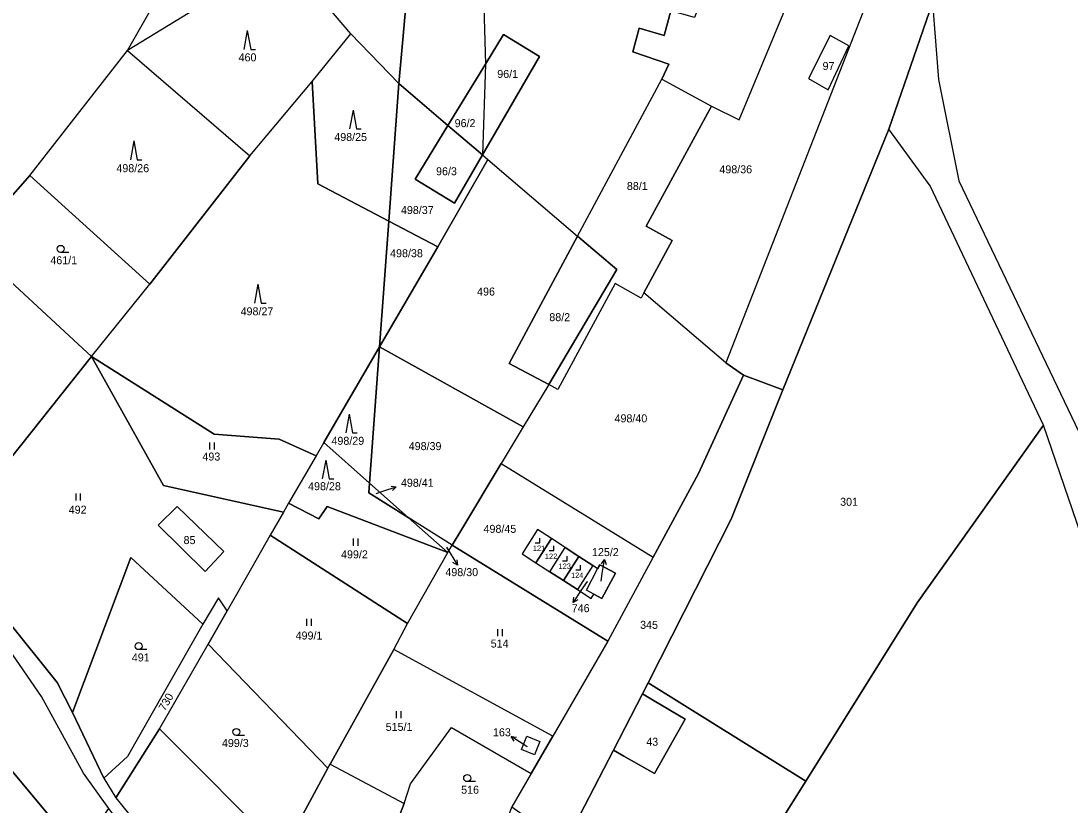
# Model space of a CAD drawing. Extents: x -590606 to -587796, y -1065936 to -1062515.
# Drawn here: x -589413.2 to -589190.3, y -1064919.2 to -1064752.6 of the extents above; entities that cross this region are included whole.
import ezdxf

# ---------------------------------------------------------------- set-up
doc = ezdxf.new("R2010")
doc.units = 0
for name, color, linetype in [('Parcela nároku', 7, 'Continuous'), ('Parcelní číslo', 7, 'Continuous'), ('Vnější obvod_ Studené', 7, 'Continuous'), ('Vrstva 30', 7, 'Continuous')]:
    doc.layers.add(name, color=color, linetype=linetype)

msp = doc.modelspace()

# ---------------------------------------------------------------- linework, layer by layer
at = {"layer": 'Parcela nároku'}
for points in [[(-589123.59, -1064757.72), (-589141.72, -1064723.62), (-589157.85, -1064685.09), (-589185.23, -1064641.99), (-589186.36, -1064642.57), (-589219.53, -1064748.72), (-589218.27, -1064765.02), (-589213.92, -1064786.57), (-589188.45, -1064839.84), (-589159.82, -1064824.9), (-589138.93, -1064817.47), (-589090.35, -1064802), (-589107.58, -1064783.08)], [(-589350.86, -1064690.27), (-589328.36, -1064715.8), (-589332.88, -1064765.85), (-589343.1, -1064755.32), (-589357.37, -1064738.5), (-589373.96, -1064719.72), (-589357.1, -1064685.38)], [(-589390.57, -1064758.82), (-589378.38, -1064737.45), (-589411.5, -1064705.67), (-589403.44, -1064690.75), (-589373.96, -1064719.72), (-589357.37, -1064738.5)], [(-589378.38, -1064737.45), (-589411.5, -1064705.67), (-589425, -1064725.38), (-589416.09, -1064747.85), (-589424.1, -1064799.94), (-589411.31, -1064785.43), (-589390.57, -1064758.82)], [(-589253.42, -1064707.43), (-589270.07, -1064751.82), (-589275.16, -1064750.39), (-589276.55, -1064755.62), (-589281.83, -1064754.11), (-589283.17, -1064759.09), (-589275.55, -1064761.71), (-589277.01, -1064764.94), (-589266.51, -1064770.69), (-589260.6, -1064773.58), (-589243.01, -1064731.06)], [(-589328.36, -1064715.8), (-589327.02, -1064717.33), (-589315.01, -1064744.55), (-589314.53, -1064761.77), (-589322.47, -1064774.76), (-589332.88, -1064765.85)], [(-589280.35, -1064796.2), (-589266.51, -1064770.69), (-589260.6, -1064773.58), (-589243.01, -1064731.06), (-589234.34, -1064750.74), (-589263.43, -1064825.24), (-589280.83, -1064810.36), (-589274.81, -1064799.22)], [(-589357.37, -1064738.5), (-589390.57, -1064758.82), (-589364.57, -1064781.21), (-589351.34, -1064765.42), (-589343.1, -1064755.32)], [(-589218.27, -1064765.02), (-589213.92, -1064786.57), (-589188.45, -1064839.84), (-589186.9, -1064843.85), (-589160.9, -1064918.18), (-589148.42, -1064969.62), (-589144.75, -1065009.02), (-589145.9, -1065034.24), (-589156.15, -1065074.53), (-589176.99, -1065132.2), (-589180.29, -1065141.18), (-589191.9, -1065194.84), (-589196.32, -1065193.25), (-589184.2, -1065137.36), (-589161.34, -1065072.9), (-589151.23, -1065033.97), (-589150.92, -1065007.3), (-589154.33, -1064973.17), (-589164.98, -1064928.86), (-589195.94, -1064838.44), (-589220.02, -1064787.63), (-589228.83, -1064775.58), (-589219.53, -1064748.72)], [(-589343.1, -1064755.32), (-589332.88, -1064765.85), (-589335.03, -1064795.08), (-589350.13, -1064787.19), (-589351.34, -1064765.42)], [(-589314.53, -1064761.77), (-589315.13, -1064781.03), (-589303, -1064760.12), (-589310.67, -1064755.45)], [(-589241.27, -1064755.67), (-589245.85, -1064764.78), (-589241.73, -1064767.22), (-589237.32, -1064757.82)], [(-589245.85, -1064764.78), (-589241.73, -1064767.22), (-589237.32, -1064757.82), (-589241.27, -1064755.67)], [(-589411.31, -1064785.43), (-589390.57, -1064758.82), (-589364.57, -1064781.21), (-589385.83, -1064808.46)], [(-589322.47, -1064774.76), (-589314.53, -1064761.77), (-589315.13, -1064781.03)], [(-589398.19, -1064823.87), (-589385.83, -1064808.46), (-589364.57, -1064781.21), (-589351.34, -1064765.42), (-589350.13, -1064787.19), (-589335.03, -1064795.08), (-589336.99, -1064821.82), (-589348.84, -1064842.17), (-589350.46, -1064844.95), (-589358.35, -1064841.46), (-589372.17, -1064840.36)], [(-589277.01, -1064764.94), (-589266.51, -1064770.69), (-589280.35, -1064796.2), (-589274.81, -1064799.22), (-589280.83, -1064810.36), (-589281.44, -1064811.5), (-589286.95, -1064808.37), (-589299.14, -1064830.85), (-589301.06, -1064829.83), (-589286.63, -1064805.4), (-589294.93, -1064798.3)], [(-589332.88, -1064765.85), (-589322.47, -1064774.76), (-589329.44, -1064786.17), (-589321.1, -1064791.31), (-589315.13, -1064781.03), (-589313.99, -1064782.01), (-589324.59, -1064800.54), (-589335.03, -1064795.08)], [(-589329.44, -1064786.17), (-589322.47, -1064774.76), (-589315.13, -1064781.03), (-589321.1, -1064791.31)], [(-589220.02, -1064787.63), (-589228.83, -1064775.58), (-589251.32, -1064830.96), (-589262.31, -1064858.44), (-589279.95, -1064893.24), (-589246.47, -1064914.08), (-589222.78, -1064876.19), (-589195.94, -1064838.44)], [(-589324.59, -1064800.54), (-589313.99, -1064782.01), (-589294.93, -1064798.3), (-589309.46, -1064825.36), (-589301.06, -1064829.83), (-589306.47, -1064838.82), (-589336.99, -1064821.82)], [(-589411.31, -1064785.43), (-589424.1, -1064799.94), (-589398.19, -1064823.87), (-589385.83, -1064808.46)], [(-589336.99, -1064821.82), (-589335.03, -1064795.08), (-589324.59, -1064800.54)], [(-589294.93, -1064798.3), (-589286.63, -1064805.4), (-589301.06, -1064829.83), (-589309.46, -1064825.36)], [(-589424.1, -1064799.94), (-589398.19, -1064823.87), (-589417.74, -1064848.39), (-589424.79, -1064835.96), (-589433.05, -1064840.7), (-589436.92, -1064834.69), (-589442.72, -1064838.68), (-589450.87, -1064826.05)], [(-589306.47, -1064838.82), (-589311.16, -1064846.62), (-589278.85, -1064866.5), (-589269.28, -1064848.75), (-589259.68, -1064827.84), (-589263.43, -1064825.24), (-589280.83, -1064810.36), (-589281.44, -1064811.5), (-589286.95, -1064808.37), (-589299.14, -1064830.85), (-589301.06, -1064829.83)], [(-589348.84, -1064842.17), (-589336.99, -1064821.82), (-589339.11, -1064850.8)], [(-589339.11, -1064850.8), (-589336.99, -1064821.82), (-589306.47, -1064838.82), (-589311.16, -1064846.62), (-589319.53, -1064860.53), (-589321.58, -1064863.94), (-589330.91, -1064858.07)], [(-589417.74, -1064848.39), (-589398.19, -1064823.87), (-589382.87, -1064851.27), (-589357.44, -1064856.96), (-589360.23, -1064861.82), (-589364.23, -1064868.85), (-589369.41, -1064877.92), (-589371.23, -1064875.18), (-589374.55, -1064880.76), (-589389.82, -1064866.59), (-589402.24, -1064899.51), (-589405.49, -1064893.12), (-589416.34, -1064879.6), (-589428.15, -1064861.27)], [(-589372.17, -1064840.36), (-589358.35, -1064841.46), (-589350.46, -1064844.95), (-589356.32, -1064855.04), (-589357.44, -1064856.96), (-589382.87, -1064851.27), (-589398.19, -1064823.87)], [(-589259.68, -1064827.84), (-589269.28, -1064848.75), (-589278.85, -1064866.5), (-589288.48, -1064884.36), (-589300.17, -1064904.53), (-589304.81, -1064912.46), (-589308.87, -1064919.53), (-589300.67, -1064925.35), (-589297.56, -1064927.36), (-589287.32, -1064907.52), (-589281.16, -1064895.58), (-589279.95, -1064893.24), (-589262.31, -1064858.44), (-589251.32, -1064830.96)], [(-589222.78, -1064876.19), (-589246.47, -1064914.08), (-589267.42, -1064947.46), (-589288.75, -1064981.4), (-589284.72, -1064984.27), (-589279.85, -1065008.58), (-589232.77, -1065042.25), (-589205.41, -1065000.22), (-589178.94, -1064950.61), (-589164.98, -1064928.86), (-589195.94, -1064838.44)], [(-589330.91, -1064858.07), (-589339.26, -1064852.82), (-589339.11, -1064850.8), (-589348.84, -1064842.17), (-589350.46, -1064844.95), (-589356.32, -1064855.04), (-589349.93, -1064858.34), (-589348.13, -1064855.73), (-589322.49, -1064865.54)], [(-589321.58, -1064863.94), (-589319.53, -1064860.53), (-589311.16, -1064846.62), (-589278.85, -1064866.5), (-589288.48, -1064884.36)], [(-589330.91, -1064858.07), (-589339.11, -1064850.8), (-589339.26, -1064852.82)], [(-589379.98, -1064855.72), (-589370.05, -1064865.3), (-589374.06, -1064869.54), (-589384.04, -1064859.73)], [(-589370.05, -1064865.3), (-589374.06, -1064869.54), (-589384.04, -1064859.73), (-589379.98, -1064855.72)], [(-589356.32, -1064855.04), (-589357.44, -1064856.96), (-589360.23, -1064861.82), (-589331.05, -1064880.62), (-589322.49, -1064865.54), (-589348.13, -1064855.73), (-589349.93, -1064858.34)], [(-589321.58, -1064863.94), (-589330.91, -1064858.07), (-589322.49, -1064865.54)], [(-589303.45, -1064860.63), (-589306.73, -1064865.78), (-589303.79, -1064867.68), (-589300.51, -1064862.55)], [(-589292.03, -1064875.29), (-589291.45, -1064874.4), (-589289.76, -1064875.31), (-589286.89, -1064869.89), (-589290.21, -1064868.11), (-589290.67, -1064868.98), (-589291.7, -1064868.31), (-589294.64, -1064866.4), (-589297.58, -1064864.47), (-589300.51, -1064862.55), (-589303.45, -1064860.63), (-589306.73, -1064865.78), (-589303.79, -1064867.68), (-589300.85, -1064869.59), (-589297.92, -1064871.49), (-589294.97, -1064873.39)], [(-589419.51, -1064880.71), (-589429.73, -1064863.35), (-589441.1, -1064876.11), (-589455.18, -1064891.01), (-589467.9, -1064901.87), (-589466.69, -1064904.1), (-589451.25, -1064936.39), (-589448.63, -1064940.01), (-589428.23, -1064968.24), (-589418.35, -1064953.57), (-589406.51, -1064936.87), (-589411.18, -1064930.48), (-589420.99, -1064918.63), (-589422.85, -1064920.26), (-589426.28, -1064916.08), (-589417.57, -1064908.93), (-589404.77, -1064924.29), (-589403.91, -1064923.64), (-589400.68, -1064928.65), (-589394.5, -1064919.94), (-589399.91, -1064912.39), (-589408.85, -1064896.13)], [(-589331.05, -1064880.62), (-589360.23, -1064861.82), (-589364.23, -1064868.85), (-589369.41, -1064877.92), (-589373.39, -1064885.02), (-589347.99, -1064911.38), (-589347.53, -1064910.53), (-589333.95, -1064886.14)], [(-589297.58, -1064864.47), (-589300.51, -1064862.55), (-589303.79, -1064867.68), (-589300.85, -1064869.59)], [(-589331.05, -1064880.62), (-589322.49, -1064865.54), (-589321.58, -1064863.94), (-589288.48, -1064884.36), (-589300.17, -1064904.53), (-589333.95, -1064886.14)], [(-589300.85, -1064869.59), (-589297.58, -1064864.47), (-589294.64, -1064866.4), (-589297.92, -1064871.49)], [(-589389.82, -1064866.59), (-589374.55, -1064880.76), (-589390.52, -1064908.86), (-589395.57, -1064913.49), (-589402.24, -1064899.51)], [(-589297.92, -1064871.49), (-589294.64, -1064866.4), (-589291.7, -1064868.31), (-589294.97, -1064873.39)], [(-589291.45, -1064874.4), (-589293.07, -1064873.53), (-589290.67, -1064868.98), (-589291.7, -1064868.31), (-589294.97, -1064873.39), (-589292.03, -1064875.29)], [(-589293.07, -1064873.53), (-589290.67, -1064868.98), (-589290.21, -1064868.11), (-589286.89, -1064869.89), (-589289.76, -1064875.31), (-589291.45, -1064874.4)], [(-589374.55, -1064880.76), (-589390.52, -1064908.86), (-589395.57, -1064913.49), (-589393.02, -1064917.62), (-589383.76, -1064903.01), (-589373.39, -1064885.02), (-589369.41, -1064877.92), (-589371.23, -1064875.18)], [(-589383.76, -1064903.01), (-589373.39, -1064885.02), (-589347.99, -1064911.38), (-589357.61, -1064929.21)], [(-589300.17, -1064904.53), (-589333.95, -1064886.14), (-589347.53, -1064910.53), (-589331.74, -1064918.83), (-589330.41, -1064914.67), (-589321.7, -1064902.7), (-589304.81, -1064912.46)], [(-589279.95, -1064893.24), (-589281.16, -1064895.58), (-589278.68, -1064897.05), (-589272.09, -1064900.96), (-589278.62, -1064912.48), (-589285.08, -1064908.8), (-589287.32, -1064907.52), (-589297.56, -1064927.36), (-589267.42, -1064947.46), (-589246.47, -1064914.08)], [(-589281.16, -1064895.58), (-589287.32, -1064907.52), (-589285.08, -1064908.8), (-589278.62, -1064912.48), (-589272.09, -1064900.96), (-589278.68, -1064897.05)], [(-589357.61, -1064929.21), (-589383.76, -1064903.01), (-589393.02, -1064917.62), (-589374.79, -1064940.23), (-589366.84, -1064946.39)], [(-589335.57, -1064928.69), (-589331.74, -1064918.83), (-589330.41, -1064914.67), (-589321.7, -1064902.7), (-589304.81, -1064912.46), (-589308.87, -1064919.53), (-589315.72, -1064936.94), (-589319.44, -1064942.57), (-589322.86, -1064951.87), (-589338.42, -1064940.59), (-589341.61, -1064938.33)], [(-589306.87, -1064907.35), (-589305.73, -1064904.53), (-589302.92, -1064905.69), (-589304.06, -1064908.51)], [(-589306.87, -1064907.35), (-589305.73, -1064904.53), (-589302.92, -1064905.69), (-589304.06, -1064908.51)], [(-589403.91, -1064923.64), (-589404.77, -1064924.29), (-589417.57, -1064908.93), (-589426.28, -1064916.08), (-589422.85, -1064920.26), (-589420.99, -1064918.63), (-589411.18, -1064930.48), (-589406.51, -1064936.87), (-589400.68, -1064928.65)], [(-589366.84, -1064946.39), (-589357.61, -1064929.21), (-589347.99, -1064911.38), (-589347.53, -1064910.53), (-589331.74, -1064918.83), (-589335.57, -1064928.69), (-589341.61, -1064938.33), (-589338.42, -1064940.59), (-589343.75, -1064948.59), (-589345.73, -1064946.7), (-589353.29, -1064954.21), (-589351.12, -1064956.35), (-589352.52, -1064957.78)]]:
    msp.add_lwpolyline(points, close=True, dxfattribs=at)
for points in [[(-589315.01, -1064744.55), (-589314.53, -1064761.77), (-589310.67, -1064755.45), (-589303, -1064760.12), (-589315.13, -1064781.03), (-589313.99, -1064782.01), (-589294.93, -1064798.3), (-589277.01, -1064764.94), (-589275.55, -1064761.71), (-589283.17, -1064759.09), (-589281.83, -1064754.11), (-589276.55, -1064755.62), (-589275.16, -1064750.39)], [(-589234.34, -1064750.74), (-589263.43, -1064825.24), (-589259.68, -1064827.84), (-589251.32, -1064830.96), (-589228.83, -1064775.58), (-589219.53, -1064748.72)], [(-589416.34, -1064879.6), (-589405.49, -1064893.12), (-589402.24, -1064899.51), (-589395.57, -1064913.49), (-589393.02, -1064917.62), (-589374.79, -1064940.23), (-589366.84, -1064946.39), (-589352.52, -1064957.78), (-589339.41, -1064969.99), (-589332.39, -1064977.16), (-589334.15, -1064981.25), (-589339.45, -1064975.71), (-589357.48, -1064957.56), (-589368.16, -1064947.4), (-589379.39, -1064938.24), (-589387.73, -1064929), (-589394.5, -1064919.94), (-589399.91, -1064912.39), (-589408.85, -1064896.13), (-589419.51, -1064880.71)]]:
    msp.add_lwpolyline(points, dxfattribs=at)
at = {"layer": 'Parcelní číslo'}
for p, q in [((-589336.3, -1064852.51), (-589333.46, -1064851.55)), ((-589337.75, -1064853), (-589336.3, -1064852.51)), ((-589322.79, -1064864.38), (-589322.03, -1064865.64)), ((-589322.03, -1064865.64), (-589320.47, -1064868.2)), ((-589289.69, -1064869.98), (-589289.23, -1064867.02)), ((-589289.94, -1064871.58), (-589289.69, -1064869.98)), ((-589292.93, -1064871.67), (-589294.21, -1064873.62)), ((-589294.21, -1064873.62), (-589295.85, -1064876.13)), ((-589306.49, -1064906.27), (-589309.02, -1064904.65)), ((-589305.63, -1064906.83), (-589306.49, -1064906.27))]:
    msp.add_line(p, q, dxfattribs=at)
for points in [[(-589334.57, -1064851.4), (-589333.46, -1064851.55), (-589334.25, -1064852.34)], [(-589320.56, -1064867.09), (-589320.47, -1064868.2), (-589321.42, -1064867.61)], [(-589289.88, -1064867.93), (-589289.23, -1064867.02), (-589288.89, -1064868.08)], [(-589294.88, -1064875.57), (-589295.85, -1064876.13), (-589295.72, -1064875.02)], [(-589308.44, -1064905.61), (-589309.02, -1064904.65), (-589307.91, -1064904.77)]]:
    msp.add_lwpolyline(points, dxfattribs=at)
at = {"layer": 'Vnější obvod_ Studené'}
for p, q in [((-589219.53, -1064748.72), (-589228.83, -1064775.58)), ((-589228.83, -1064775.58), (-589251.32, -1064830.96)), ((-589251.32, -1064830.96), (-589262.31, -1064858.44)), ((-589262.31, -1064858.44), (-589279.95, -1064893.24)), ((-589279.95, -1064893.24), (-589263.21, -1064903.66)), ((-589263.21, -1064903.66), (-589246.47, -1064914.08)), ((-589246.47, -1064914.08), (-589267.42, -1064947.46))]:
    msp.add_line(p, q, dxfattribs=at)
at = {"layer": 'Vrstva 30'}
for p, q in [((-589365.1, -1064754.62), (-589365.83, -1064758.62)), ((-589365.1, -1064754.62), (-589364.37, -1064758.62)), ((-589364.37, -1064758.62), (-589363.37, -1064758.62)), ((-589342.63, -1064771.51), (-589343.36, -1064775.51)), ((-589342.63, -1064771.51), (-589341.9, -1064775.51)), ((-589341.9, -1064775.51), (-589340.9, -1064775.51)), ((-589389.2, -1064778.05), (-589389.94, -1064782.05)), ((-589389.2, -1064778.05), (-589388.47, -1064782.05)), ((-589388.47, -1064782.05), (-589387.47, -1064782.05)), ((-589403, -1064801.75), (-589404.75, -1064801.75)), ((-589362.85, -1064808.53), (-589363.58, -1064812.53)), ((-589362.85, -1064808.53), (-589362.12, -1064812.53)), ((-589362.12, -1064812.53), (-589361.12, -1064812.53)), ((-589343.46, -1064836.11), (-589344.2, -1064840.11)), ((-589343.46, -1064836.11), (-589342.73, -1064840.11)), ((-589342.73, -1064840.11), (-589341.73, -1064840.11)), ((-589373.12, -1064842.14), (-589373.12, -1064843.64)), ((-589372.09, -1064843.64), (-589372.09, -1064842.14)), ((-589348.44, -1064845.88), (-589349.18, -1064849.88)), ((-589348.44, -1064845.88), (-589347.71, -1064849.88)), ((-589347.71, -1064849.88), (-589346.71, -1064849.88)), ((-589401.55, -1064852.97), (-589401.55, -1064854.47)), ((-589400.53, -1064854.47), (-589400.53, -1064852.97)), ((-589342.61, -1064862.57), (-589342.61, -1064864.07)), ((-589341.58, -1064864.07), (-589341.58, -1064862.57)), ((-589352.52, -1064879.6), (-589352.52, -1064881.1)), ((-589351.49, -1064881.1), (-589351.49, -1064879.6)), ((-589311.93, -1064881.79), (-589311.93, -1064883.29)), ((-589310.91, -1064883.29), (-589310.91, -1064881.79)), ((-589386.44, -1064886.16), (-589388.19, -1064886.16)), ((-589333.44, -1064899.24), (-589333.44, -1064900.74)), ((-589332.42, -1064900.74), (-589332.42, -1064899.24)), ((-589365.68, -1064904.4), (-589367.43, -1064904.4)), ((-589316.63, -1064914.21), (-589318.38, -1064914.21))]:
    msp.add_line(p, q, dxfattribs=at)
for points in [[(-589303.92, -1064863.48), (-589302.92, -1064863.48), (-589302.92, -1064862.48)], [(-589301, -1064865.09), (-589300, -1064865.09), (-589300, -1064864.09)], [(-589298.14, -1064867.3), (-589297.14, -1064867.3), (-589297.14, -1064866.3)], [(-589295.34, -1064869.2), (-589294.34, -1064869.2), (-589294.34, -1064868.2)]]:
    msp.add_lwpolyline(points, dxfattribs=at)
for centre in [(-589404.75, -1064801), (-589388.19, -1064885.41), (-589367.43, -1064903.65), (-589318.38, -1064913.46)]:
    msp.add_circle(centre, 0.75, dxfattribs=at)

# ---------------------------------------------------------------- texts
at = {"layer": 'Parcela nároku'}
for s, height, p in [('460', 1.7, (-589366.95, -1064761.15)), ('96/1', 1.7, (-589312, -1064764.67)), ('97', 1.7, (-589242.89, -1064762.98)), ('96/2', 1.7, (-589321.05, -1064775.13)), ('498/25', 1.7, (-589346.62, -1064778.07)), ('498/26', 1.7, (-589392.91, -1064784.7)), ('498/36', 1.7, (-589264.81, -1064784.94)), ('96/3', 1.7, (-589325, -1064785.35)), ('88/1', 1.7, (-589284.46, -1064788.49)), ('498/37', 1.7, (-589332.46, -1064793.59)), ('498/38', 1.7, (-589334.76, -1064802.77)), ('461/1', 1.7, (-589406.94, -1064804.26)), ('496', 1.7, (-589316.28, -1064810.91)), ('498/27', 1.7, (-589366.52, -1064815.12)), ('88/2', 1.7, (-589300.94, -1064816.36)), ('498/40', 1.7, (-589287.08, -1064837.86)), ('498/29', 1.7, (-589347.22, -1064842.63)), ('498/39', 1.7, (-589330.81, -1064843.76)), ('493', 1.7, (-589374.63, -1064845.97)), ('498/28', 1.7, (-589352.18, -1064852.28)), ('498/41', 0.1, (-589337.95, -1064853)), ('301', 1.7, (-589239.16, -1064855.59)), ('492', 1.7, (-589403.04, -1064857.27)), ('498/45', 1.7, (-589314.91, -1064861.34)), ('85', 1.7, (-589378.64, -1064863.73)), ('499/2', 1.7, (-589345.18, -1064866.76)), ('498/30', 0.1, (-589323.01, -1064864.38)), ('121', 1.14, (-589304.44, -1064865.18)), ('122', 1.14, (-589301.88, -1064866.9)), ('123', 1.14, (-589298.98, -1064869)), ('124', 1.14, (-589296.33, -1064870.92)), ('746', 0.1, (-589293.03, -1064871.67)), ('125/2', 0.1, (-589290.11, -1064871.58)), ('345', 1.7, (-589281.65, -1064881.74)), ('499/1', 1.7, (-589354.83, -1064884.01)), ('514', 1.7, (-589313.39, -1064885.71)), ('491', 1.7, (-589389.63, -1064888.67)), ('515/1', 1.7, (-589335.7, -1064903.42)), ('499/3', 1.7, (-589370.49, -1064906.85)), ('43', 1.7, (-589280.34, -1064906.58)), ('163', 0.1, (-589305.72, -1064906.83)), ('516', 1.7, (-589319.67, -1064916.78))]:
    msp.add_text(s, height=height, dxfattribs=at).set_placement(p)
msp.add_text('730', height=1.7, rotation=59.8863, dxfattribs=at).set_placement((-589382.59, -1064899.33))
at = {"layer": 'Parcelní číslo'}
for s, p in [('498/41', (-589332.46, -1064851.55)), ('125/2', (-589291.87, -1064866.28)), ('498/30', (-589323.02, -1064870.54)), ('746', (-589296.18, -1064878.2)), ('163', (-589312.91, -1064904.57))]:
    msp.add_text(s, height=1.7, dxfattribs=at).set_placement(p)

doc.saveas('drawing.dxf')
